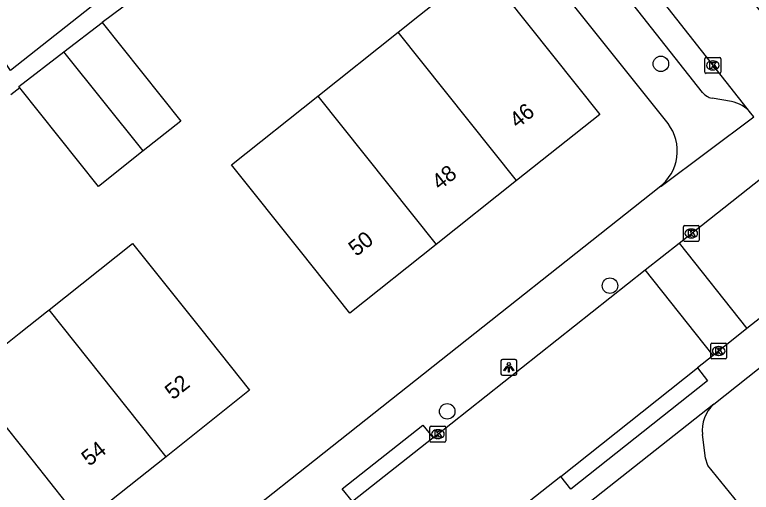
# Model space of a CAD drawing. Extents: x 159503 to 160347, y 382525 to 383272.
# Drawn here: x 159784.15 to 159830.67, y 383005.91 to 383036.1 of the extents above; entities that cross this region are included whole.
import ezdxf

# ---------------------------------------------------------------- set-up
doc = ezdxf.new("R2010")
doc.units = 0
for name, color, linetype in [('IMGEO_Boom', 7, 'Continuous'), ('IMGEO_Kolk', 7, 'Continuous'), ('IMGEO_Lichtpunt', 7, 'Continuous'), ('IMGEO_Pand', 7, 'Continuous'), ('IMGEO_Pand_nummerreeks', 7, 'Continuous'), ('IMGEO_Rijbaan_lokaal_open', 7, 'Continuous'), ('IMGEO_Voetpad_open', 7, 'Continuous')]:
    doc.layers.add(name, color=color, linetype=linetype)

msp = doc.modelspace()

# ---------------------------------------------------------------- linework, layer by layer
at = {"layer": 'IMGEO_Boom'}
for centre in [(159824.963, 383032.998), (159821.748, 383018.971), (159811.465, 383011.025)]:
    msp.add_circle(centre, 0.489, dxfattribs=at)
at = {"layer": 'IMGEO_Kolk'}
for p, q in [((159827.743, 383032.47), (159827.743, 383033.322)), ((159827.818, 383033.396), (159828.67, 383033.396)), ((159828.231, 383033.176), (159828.256, 383033.176)), ((159828.744, 383033.322), (159828.744, 383032.47)), ((159828.67, 383032.396), (159827.818, 383032.396)), ((159828.254, 383032.616), (159828.229, 383032.616)), ((159826.384, 383021.848), (159826.384, 383022.7)), ((159826.459, 383022.774), (159827.311, 383022.774)), ((159826.872, 383022.554), (159826.897, 383022.554)), ((159827.385, 383022.7), (159827.385, 383021.848)), ((159826.895, 383021.994), (159826.87, 383021.994)), ((159827.311, 383021.774), (159826.459, 383021.774)), ((159828.115, 383014.416), (159828.115, 383015.268)), ((159828.19, 383015.342), (159829.042, 383015.342)), ((159828.603, 383015.122), (159828.628, 383015.122)), ((159829.116, 383015.268), (159829.116, 383014.416)), ((159828.626, 383014.562), (159828.601, 383014.562)), ((159829.042, 383014.342), (159828.19, 383014.342)), ((159810.375, 383009.162), (159810.375, 383010.014)), ((159810.45, 383010.088), (159811.302, 383010.088)), ((159811.376, 383010.014), (159811.376, 383009.162)), ((159810.863, 383009.868), (159810.888, 383009.868)), ((159811.302, 383009.088), (159810.45, 383009.088)), ((159810.886, 383009.308), (159810.861, 383009.308))]:
    msp.add_line(p, q, dxfattribs=at)
for points in [[(159827.743, 383032.47), (159827.743, 383033.322)], [(159827.818, 383033.396), (159828.67, 383033.396)], [(159828.744, 383033.322), (159828.744, 383032.47)], [(159828.064, 383033.096), (159828.187, 383033.096), (159828.187, 383032.945), (159828.317, 383033.096), (159828.481, 383033.096), (159828.335, 383032.945), (159828.488, 383032.696), (159828.336, 383032.696), (159828.251, 383032.86), (159828.187, 383032.793), (159828.187, 383032.696), (159828.064, 383032.696), (159828.064, 383033.096)], [(159828.67, 383032.396), (159827.818, 383032.396)], [(159826.384, 383021.848), (159826.384, 383022.7)], [(159826.459, 383022.774), (159827.311, 383022.774)], [(159826.705, 383022.474), (159826.828, 383022.474), (159826.828, 383022.323), (159826.958, 383022.474), (159827.122, 383022.474), (159826.976, 383022.323), (159827.129, 383022.074), (159826.977, 383022.074), (159826.892, 383022.238), (159826.828, 383022.171), (159826.828, 383022.074), (159826.705, 383022.074), (159826.705, 383022.474)], [(159827.385, 383022.7), (159827.385, 383021.848)], [(159827.311, 383021.774), (159826.459, 383021.774)], [(159828.115, 383014.416), (159828.115, 383015.268)], [(159828.19, 383015.342), (159829.042, 383015.342)], [(159828.436, 383015.042), (159828.559, 383015.042), (159828.559, 383014.891), (159828.689, 383015.042), (159828.853, 383015.042), (159828.707, 383014.891), (159828.86, 383014.642), (159828.708, 383014.642), (159828.623, 383014.806), (159828.559, 383014.739), (159828.559, 383014.642), (159828.436, 383014.642), (159828.436, 383015.042)], [(159829.116, 383015.268), (159829.116, 383014.416)], [(159829.042, 383014.342), (159828.19, 383014.342)], [(159810.375, 383009.162), (159810.375, 383010.014)], [(159810.45, 383010.088), (159811.302, 383010.088)], [(159811.376, 383010.014), (159811.376, 383009.162)], [(159810.696, 383009.788), (159810.819, 383009.788), (159810.819, 383009.637), (159810.949, 383009.788), (159811.113, 383009.788), (159810.967, 383009.637), (159811.12, 383009.388), (159810.968, 383009.388), (159810.883, 383009.552), (159810.819, 383009.485), (159810.819, 383009.388), (159810.696, 383009.388), (159810.696, 383009.788)], [(159811.302, 383009.088), (159810.45, 383009.088)]]:
    msp.add_lwpolyline(points, dxfattribs=at)
for centre, start, end in [((159827.82, 383033.32), 91.552, 178.448), ((159827.82, 383033.32), 91.552, 178.448), ((159828.668, 383033.32), 1.552, 88.448), ((159828.668, 383033.32), 1.552, 88.448), ((159827.82, 383032.472), 181.552, 268.448), ((159827.82, 383032.472), 181.552, 268.448), ((159828.668, 383032.472), 271.552, 358.448), ((159828.668, 383032.472), 271.552, 358.448), ((159826.461, 383022.698), 91.552, 178.448), ((159826.461, 383022.698), 91.552, 178.448), ((159827.309, 383022.698), 1.552, 88.448), ((159827.309, 383022.698), 1.552, 88.448), ((159826.461, 383021.85), 181.552, 268.448), ((159826.461, 383021.85), 181.552, 268.448), ((159827.309, 383021.85), 271.552, 358.448), ((159827.309, 383021.85), 271.552, 358.448), ((159828.192, 383015.266), 91.552, 178.448), ((159828.192, 383015.266), 91.552, 178.448), ((159829.04, 383015.266), 1.552, 88.448), ((159829.04, 383015.266), 1.552, 88.448), ((159828.192, 383014.418), 181.552, 268.448), ((159828.192, 383014.418), 181.552, 268.448), ((159829.04, 383014.418), 271.552, 358.448), ((159829.04, 383014.418), 271.552, 358.448), ((159810.452, 383010.012), 91.552, 178.448), ((159810.452, 383010.012), 91.552, 178.448), ((159811.3, 383010.012), 1.552, 88.448), ((159811.3, 383010.012), 1.552, 88.448), ((159810.452, 383009.164), 181.552, 268.448), ((159810.452, 383009.164), 181.552, 268.448), ((159811.3, 383009.164), 271.552, 358.448), ((159811.3, 383009.164), 271.552, 358.448)]:
    msp.add_arc(centre, 0.0765, start, end, dxfattribs=at)
for centre, major_axis, ratio, start_param, end_param in [((159828.23, 383032.896), (-0.387, 0.002), 0.722429, 4.712389, 7.853982), ((159828.255, 383032.896), (-0.39, 0.002), 0.717154, 1.570796, 4.712389), ((159826.871, 383022.274), (-0.387, 0.002), 0.722429, 4.712389, 7.853982), ((159826.896, 383022.274), (-0.39, 0.002), 0.717154, 1.570796, 4.712389), ((159828.602, 383014.842), (-0.387, 0.002), 0.722429, 4.712389, 7.853982), ((159828.627, 383014.842), (-0.39, 0.002), 0.717154, 1.570796, 4.712389), ((159810.862, 383009.588), (-0.387, 0.002), 0.722429, 4.712389, 7.853982), ((159810.887, 383009.588), (-0.39, 0.002), 0.717154, 1.570796, 4.712389)]:
    msp.add_ellipse(centre, major_axis=major_axis, ratio=ratio, start_param=start_param, end_param=end_param, dxfattribs=at)
at = {"layer": 'IMGEO_Lichtpunt'}
for p, q in [((159814.86, 383014.215), (159814.86, 383013.408)), ((159814.86, 383014.215), (159814.86, 383013.408)), ((159815.762, 383014.31), (159814.954, 383014.31)), ((159815.762, 383014.31), (159814.954, 383014.31)), ((159815.856, 383013.408), (159815.856, 383014.215)), ((159815.856, 383013.408), (159815.856, 383014.215)), ((159814.954, 383013.314), (159815.762, 383013.314)), ((159814.954, 383013.314), (159815.762, 383013.314))]:
    msp.add_line(p, q, dxfattribs=at)
for points in [[(159815.234, 383013.879), (159815.273, 383013.851), (159815.085, 383013.589), (159815.047, 383013.616), (159815.234, 383013.879)], [(159815.336, 383013.831), (159815.383, 383013.831), (159815.383, 383013.509), (159815.336, 383013.509), (159815.336, 383013.831)], [(159815.446, 383013.851), (159815.484, 383013.878), (159815.671, 383013.616), (159815.632, 383013.588), (159815.446, 383013.851)]]:
    msp.add_lwpolyline(points, dxfattribs=at)
msp.add_circle((159815.359, 383014.013), 0.0994, dxfattribs=at)
for centre, start, end in [((159814.954, 383014.215), 90, 180), ((159814.954, 383014.215), 90, 180), ((159815.762, 383014.215), 0, 90), ((159815.762, 383014.215), 0, 90), ((159814.954, 383013.408), 180, 270), ((159814.954, 383013.408), 180, 270), ((159815.762, 383013.408), 270, 0), ((159815.762, 383013.408), 270, 360)]:
    msp.add_arc(centre, 0.0946, start, end, dxfattribs=at)
at = {"layer": 'IMGEO_Pand'}
for points in [[(159808.372, 383035.002), (159809.712, 383036.069), (159813.623, 383039.183), (159821.096, 383029.798), (159815.847, 383025.618)], [(159787.257, 383033.765), (159789.66, 383035.615)], [(159789.66, 383035.615), (159794.638, 383029.38), (159792.268, 383027.488)], [(159803.298, 383030.962), (159808.372, 383035.002)], [(159815.847, 383025.618), (159808.372, 383035.002)], [(159784.459, 383031.484), (159784.396, 383031.563), (159787.257, 383033.765)], [(159792.268, 383027.488), (159787.257, 383033.765)], [(159792.268, 383027.488), (159789.447, 383025.236), (159784.459, 383031.484)], [(159810.773, 383021.578), (159805.314, 383017.231), (159802.199, 383021.143), (159797.841, 383026.616), (159803.298, 383030.962)], [(159803.298, 383030.962), (159810.773, 383021.578)], [(159815.847, 383025.618), (159810.773, 383021.578)], [(159786.318, 383017.448), (159791.593, 383021.645), (159793.024, 383019.848), (159795.872, 383016.269), (159798.986, 383012.357), (159793.71, 383008.158)], [(159793.71, 383008.158), (159788.437, 383003.961), (159785.323, 383007.874), (159782.767, 383011.085), (159781.958, 383010.441), (159780.23, 383012.611), (159783.363, 383015.106), (159784.429, 383015.955), (159786.145, 383017.31), (159786.318, 383017.448)], [(159793.71, 383008.158), (159786.318, 383017.448)]]:
    msp.add_lwpolyline(points, dxfattribs=at)
at = {"layer": 'IMGEO_Rijbaan_lokaal_open'}
for points in [[(159830.638, 383029.888), (159815.85, 383048.725)], [(159830.825, 383029.654), (159830.638, 383029.888)], [(159826.116, 383021.665), (159831.353, 383025.815)], [(159823.977, 383019.969), (159826.116, 383021.665)], [(159826.116, 383021.665), (159830.398, 383016.259)], [(159810.572, 383009.347), (159823.977, 383019.969)], [(159828.26, 383014.561), (159823.977, 383019.969)], [(159831.979, 383017.516), (159830.398, 383016.259)], [(159830.398, 383016.259), (159828.26, 383014.561)], [(159828.26, 383014.561), (159827.27, 383013.774)], [(159818.638, 383006.917), (159827.27, 383013.774)], [(159828.299, 383011.476), (159819.587, 383004.581)], [(159830.239, 383005.093), (159829.835, 383005.251), (159827.929, 383007.611), (159827.778, 383008.07), (159827.59, 383009.566)], [(159810.572, 383009.347), (159805.481, 383005.321)], [(159818.638, 383006.917), (159816.646, 383005.334)]]:
    msp.add_lwpolyline(points, dxfattribs=at)
for centre, radius, start, end in [((160916.425, 383895.763), 1384.294, 217.589166, 218.585443), ((159829.754, 383009.849), 2.182, 131.8089, 187.4609)]:
    msp.add_arc(centre, radius, start, end, dxfattribs=at)
at = {"layer": 'IMGEO_Voetpad_open'}
for points in [[(159827.584, 383031.188), (159817.373, 383044.155), (159816.154, 383045.703)], [(159825.415, 383029.215), (159817.757, 383038.825), (159815.647, 383041.472), (159812.858, 383045.15)], [(159795.222, 383042.699), (159795.675, 383041.908), (159783.872, 383032.57), (159780.389, 383037.79)], [(159795.712, 383040.116), (159789.66, 383035.615)], [(159784.459, 383031.484), (159783.896, 383031.034)], [(159829.42, 383030.611), (159828.194, 383030.825)], [(159824.858, 383025.202), (159824.98, 383025.268), (159830.825, 383029.654)], [(159774.942, 382985.649), (159793.053, 383000), (159824.858, 383025.202)], [(159828.299, 383011.476), (159833.207, 383015.378)], [(159827.27, 383013.774), (159827.917, 383012.96), (159819.285, 383006.103), (159818.638, 383006.917)], [(159805.481, 383005.321), (159804.836, 383006.137), (159809.927, 383010.163), (159810.572, 383009.347)]]:
    msp.add_lwpolyline(points, dxfattribs=at)
for centre, radius, start, end in [((159828.454, 383031.955), 1.16, 221.4216, 257.0662), ((159829.074, 383028.641), 2, 38.5713, 80.0423), ((159823.148, 383027.484), 2.852, 306.8332, 37.3625)]:
    msp.add_arc(centre, radius, start, end, dxfattribs=at)

# ---------------------------------------------------------------- texts
at = {"layer": 'IMGEO_Pand_nummerreeks'}
for s, rotation, p in [('46', 38.5318, (159815.901, 383028.883)), ('48', 38.5299, (159810.991, 383024.972)), ('50', 38.5299, (159805.73, 383020.783)), ('52', 38.5165, (159794.13, 383011.714)), ('54', 38.5142, (159788.858, 383007.518))]:
    msp.add_text(s, height=1, rotation=rotation, dxfattribs=at).set_placement(p)

doc.saveas('drawing.dxf')
